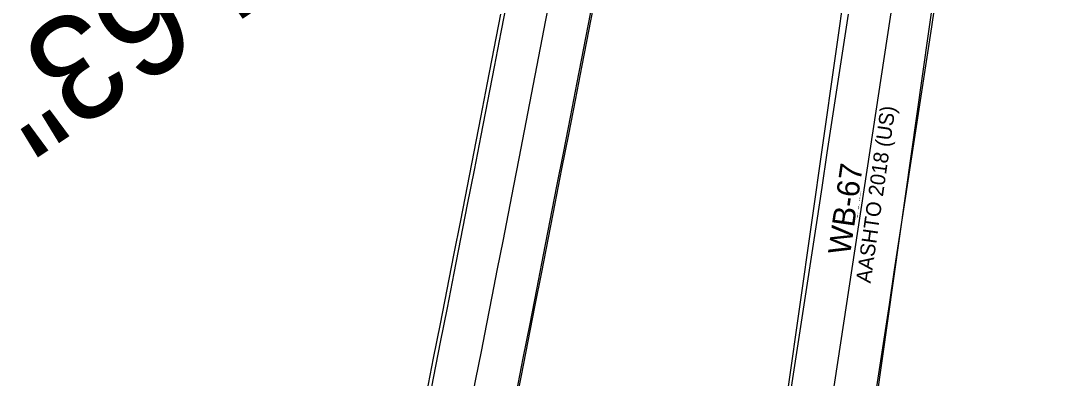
# Model space of a CAD drawing. Extents: x -69 to 14108008, y -6 to 8640172.
# Drawn here: x 14107816.7 to 14107914.7, y 8639617.1 to 8639651.1 of the extents above; entities that cross this region are included whole.
import ezdxf

# ---------------------------------------------------------------- set-up
doc = ezdxf.new("R2010")
doc.units = 0
for name, color, linetype in [('AutoTurn', 7, 'Continuous'), ('AutoTurn1', 7, 'Continuous'), ('AutoTurn2', 7, 'Continuous'), ('TextAlignment', 7, 'Continuous')]:
    doc.layers.add(name, color=color, linetype=linetype)

msp = doc.modelspace()

# ---------------------------------------------------------------- linework, layer by layer
at = {"layer": 'AutoTurn'}
msp.add_arc((14098576.761, 8641447.78), 9462, 348.2293605, 349.264447, dxfattribs=at)
at = {"layer": 'AutoTurn1'}
for points in [[(14107869.221, 8639685.979), (14107868.6, 8639682.705), (14107867.978, 8639679.432), (14107867.354, 8639676.16), (14107866.73, 8639672.888), (14107866.104, 8639669.616), (14107865.477, 8639666.344), (14107864.849, 8639663.073), (14107864.22, 8639659.802), (14107863.59, 8639656.531), (14107862.958, 8639653.26), (14107862.326, 8639649.99), (14107861.692, 8639646.72), (14107861.057, 8639643.45), (14107860.421, 8639640.181), (14107859.784, 8639636.912), (14107859.146, 8639633.642), (14107858.506, 8639630.374), (14107857.866, 8639627.105), (14107857.224, 8639623.837), (14107856.581, 8639620.569), (14107855.937, 8639617.301), (14107855.292, 8639614.033)], [(14107877.081, 8639684.488), (14107876.46, 8639681.214), (14107875.837, 8639677.94), (14107875.214, 8639674.666), (14107874.589, 8639671.393), (14107873.963, 8639668.119), (14107873.336, 8639664.845), (14107872.707, 8639661.572), (14107872.078, 8639658.299), (14107871.447, 8639655.026), (14107870.815, 8639651.753), (14107870.182, 8639648.48), (14107869.548, 8639645.208), (14107868.912, 8639641.935), (14107868.276, 8639638.663), (14107867.638, 8639635.391), (14107867, 8639632.12), (14107866.36, 8639628.848), (14107865.718, 8639625.577), (14107865.076, 8639622.306), (14107864.433, 8639619.035), (14107863.788, 8639615.765)], [(14107871.296, 8639653.372), (14107870.661, 8639650.1), (14107870.024, 8639646.828), (14107869.387, 8639643.556), (14107868.748, 8639640.285), (14107868.109, 8639637.013), (14107867.468, 8639633.742), (14107866.827, 8639630.471), (14107866.185, 8639627.2), (14107865.541, 8639623.929), (14107864.897, 8639620.659), (14107864.251, 8639617.389), (14107863.605, 8639614.118)], [(14107862.317, 8639651.722), (14107861.681, 8639648.453), (14107861.044, 8639645.183), (14107860.406, 8639641.914), (14107859.767, 8639638.645), (14107859.127, 8639635.376), (14107858.486, 8639632.108), (14107857.844, 8639628.839), (14107857.201, 8639625.571), (14107856.557, 8639622.303), (14107855.912, 8639619.036), (14107855.266, 8639615.768)]]:
    msp.add_lwpolyline(points, dxfattribs=at)
msp.add_arc((14098576.761, 8641447.78), 9462, 348.2293605, 349.264447, dxfattribs=at)
at = {"layer": 'AutoTurn2'}
msp.add_line((14107922.677, 8639804.377), (14107890.191, 8639591.46), dxfattribs=at)
for points in [[(14107895.968, 8639660.765), (14107895.947, 8639660.768), (14107895.937, 8639660.698), (14107895.139, 8639655.087), (14107888.502, 8639608.365), (14107892.71, 8639607.767), (14107896.918, 8639607.169), (14107903.555, 8639653.892), (14107904.351, 8639659.503), (14107904.361, 8639659.573), (14107904.34, 8639659.576)], [(14107903.75, 8639653.809), (14107903.247, 8639650.513), (14107902.744, 8639647.217), (14107902.242, 8639643.921), (14107901.739, 8639640.625), (14107901.236, 8639637.33), (14107900.733, 8639634.034), (14107900.23, 8639630.738), (14107899.727, 8639627.442), (14107899.224, 8639624.146), (14107898.721, 8639620.85), (14107898.218, 8639617.554), (14107897.716, 8639614.258)], [(14107895.339, 8639651.719), (14107894.836, 8639648.424), (14107894.333, 8639645.128), (14107893.83, 8639641.832), (14107893.327, 8639638.536), (14107892.824, 8639635.24), (14107892.321, 8639631.944), (14107891.819, 8639628.648), (14107891.316, 8639625.352), (14107890.813, 8639622.056), (14107890.31, 8639618.76), (14107889.807, 8639615.465)]]:
    msp.add_lwpolyline(points, dxfattribs=at)

# ---------------------------------------------------------------- texts
for s, height, p in [('AASHTO 2018 (US)', 1.41667, (14107897.47, 8639626.115)), ('WB-67', 2.125, (14107895.522, 8639628.768)), ('(c) 2023 Transoft Solutions, Inc. All rights reserved.', 0.085, (14107896.234, 8639632.274))]:
    msp.add_text(s, height=height, rotation=81.91521, dxfattribs=at).set_placement(p)
at = {"layer": 'TextAlignment'}
msp.add_text('87°03\'07.63"', height=10.02, rotation=214.07711, dxfattribs=at).set_placement((14107875.215, 8639688.677))

doc.saveas('drawing.dxf')
